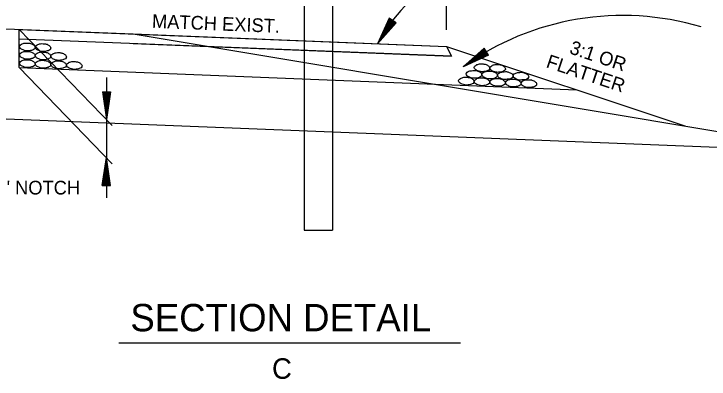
# Model space of a CAD drawing. Extents: x 1374136 to 1374281, y 380549 to 380948.
# Drawn here: x 1374151.8 to 1374182.29, y 380859.08 to 380875.1 of the extents above; entities that cross this region are included whole.
import ezdxf

# ---------------------------------------------------------------- set-up
doc = ezdxf.new("R2010")
doc.units = 0
doc.layers.add('Default', color=7, linetype='Continuous')
doc.layers.add('R_Draft', color=7, linetype='Continuous')

msp = doc.modelspace()

# ---------------------------------------------------------------- linework, layer by layer
at = {"layer": 'Default'}
for p, q in [((1374164.527, 380880.564), (1374164.527, 380865.616)), ((1374165.777, 380880.564), (1374165.777, 380865.616)), ((1374170.777, 380874.406), (1374170.777, 380876.243)), ((1374137.027, 380875.024), (1374157.027, 380874.224)), ((1374168.262, 380874.916), (1374167.748, 380873.795)), ((1374168.567, 380874.714), (1374167.748, 380873.795)), ((1374168.285, 380874.895), (1374167.86, 380873.967)), ((1374168.544, 380874.733), (1374167.86, 380873.967)), ((1374168.314, 380874.879), (1374167.974, 380874.143)), ((1374168.513, 380874.746), (1374167.974, 380874.143)), ((1374168.337, 380874.863), (1374168.083, 380874.31)), ((1374168.49, 380874.765), (1374168.083, 380874.31)), ((1374168.365, 380874.847), (1374168.197, 380874.484)), ((1374168.464, 380874.781), (1374168.197, 380874.484)), ((1374168.567, 380874.714), (1374168.262, 380874.916)), ((1374168.393, 380874.828), (1374168.311, 380874.653)), ((1374168.438, 380874.799), (1374168.311, 380874.653)), ((1374156.117, 380870.205), (1374152.027, 380874.424)), ((1374152.027, 380872.749), (1374152.027, 380874.424)), ((1374157.027, 380874.224), (1374170.777, 380873.674)), ((1374157.027, 380874.224), (1374194.756, 380867.936)), ((1374157.027, 380873.799), (1374170.994, 380873.241)), ((1374170.777, 380873.674), (1374181.227, 380870.191)), ((1374170.777, 380873.674), (1374170.994, 380873.241)), ((1374172.425, 380873.599), (1374171.502, 380872.784)), ((1374172.443, 380873.571), (1374171.674, 380872.893)), ((1374172.459, 380873.545), (1374171.848, 380873.008)), ((1374172.475, 380873.521), (1374172.018, 380873.119)), ((1374172.491, 380873.493), (1374172.19, 380873.23)), ((1374172.509, 380873.467), (1374172.365, 380873.341)), ((1374172.541, 380873.42), (1374172.365, 380873.341)), ((1374172.625, 380873.29), (1374172.425, 380873.599)), ((1374172.625, 380873.29), (1374171.502, 380872.784)), ((1374172.607, 380873.316), (1374171.674, 380872.893)), ((1374172.588, 380873.342), (1374171.848, 380873.008)), ((1374172.573, 380873.365), (1374172.018, 380873.119)), ((1374172.557, 380873.391), (1374172.19, 380873.23)), ((1374156.117, 380868.53), (1374152.027, 380872.749)), ((1374152.027, 380872.749), (1374176.488, 380871.771)), ((1374155.86, 380872.305), (1374155.86, 380867.029)), ((1374155.683, 380871.688), (1374155.86, 380870.471)), ((1374155.683, 380871.688), (1374156.045, 380871.687)), ((1374155.71, 380871.689), (1374155.859, 380870.672)), ((1374155.745, 380871.687), (1374155.861, 380870.889)), ((1374155.776, 380871.687), (1374155.861, 380871.09)), ((1374155.809, 380871.687), (1374155.863, 380871.292)), ((1374155.838, 380871.692), (1374155.864, 380871.497)), ((1374156.014, 380871.69), (1374155.859, 380870.672)), ((1374156.045, 380871.687), (1374155.86, 380870.471)), ((1374155.979, 380871.689), (1374155.861, 380870.889)), ((1374155.952, 380871.685), (1374155.861, 380871.09)), ((1374155.924, 380871.688), (1374155.863, 380871.292)), ((1374155.892, 380871.687), (1374155.864, 380871.497)), ((1374137.027, 380871.074), (1374188.212, 380869.027)), ((1374155.677, 380867.579), (1374155.86, 380868.796)), ((1374155.704, 380867.578), (1374155.858, 380868.594)), ((1374156.008, 380867.575), (1374155.858, 380868.594)), ((1374156.038, 380867.578), (1374155.86, 380868.796)), ((1374155.738, 380867.58), (1374155.859, 380868.377)), ((1374155.972, 380867.576), (1374155.859, 380868.377)), ((1374155.769, 380867.579), (1374155.858, 380868.176)), ((1374155.802, 380867.58), (1374155.859, 380867.974)), ((1374155.945, 380867.581), (1374155.858, 380868.176)), ((1374155.917, 380867.577), (1374155.859, 380867.974)), ((1374155.832, 380867.574), (1374155.858, 380867.769)), ((1374155.885, 380867.579), (1374155.858, 380867.769)), ((1374155.677, 380867.579), (1374156.038, 380867.578)), ((1374156.41, 380860.679), (1374171.395, 380860.679))]:
    msp.add_line(p, q, dxfattribs=at)
msp.add_lwpolyline([(1374152.027, 380873.999), (1374152.027, 380874.424), (1374170.777, 380873.674), (1374170.994, 380873.241)], close=True, dxfattribs=at)
for centre, radius, start, end in [((1374174.22, 380870.331), 7.341, 88.8267, 151.8416), ((1374178.504, 380863.012), 12.021, 73.3815, 125.6318)]:
    msp.add_arc(centre, radius, start, end, dxfattribs=at)
for points in [[(1374152.399, 380873.822), (1374152.279, 380873.821), (1374152.132, 380873.772), (1374152.062, 380873.707), (1374152.05, 380873.664), (1374152.085, 380873.59), (1374152.129, 380873.557), (1374152.205, 380873.519), (1374152.324, 380873.485), (1374152.383, 380873.48), (1374152.474, 380873.486), (1374152.573, 380873.503), (1374152.65, 380873.531), (1374152.72, 380873.588), (1374152.731, 380873.631), (1374152.71, 380873.697), (1374152.656, 380873.742), (1374152.606, 380873.779), (1374152.526, 380873.806), (1374152.475, 380873.818), (1374152.399, 380873.822)], [(1374153.085, 380873.795), (1374152.965, 380873.793), (1374152.818, 380873.744), (1374152.748, 380873.68), (1374152.736, 380873.636), (1374152.771, 380873.563), (1374152.815, 380873.529), (1374152.891, 380873.492), (1374153.01, 380873.457), (1374153.069, 380873.453), (1374153.16, 380873.458), (1374153.259, 380873.475), (1374153.336, 380873.503), (1374153.406, 380873.56), (1374153.417, 380873.604), (1374153.397, 380873.67), (1374153.343, 380873.714), (1374153.292, 380873.752), (1374153.212, 380873.778), (1374153.161, 380873.79), (1374153.085, 380873.795)], [(1374152.399, 380873.457), (1374152.279, 380873.456), (1374152.132, 380873.407), (1374152.062, 380873.342), (1374152.05, 380873.299), (1374152.085, 380873.225), (1374152.129, 380873.192), (1374152.205, 380873.154), (1374152.324, 380873.12), (1374152.383, 380873.115), (1374152.474, 380873.121), (1374152.573, 380873.138), (1374152.65, 380873.166), (1374152.72, 380873.223), (1374152.731, 380873.266), (1374152.71, 380873.332), (1374152.656, 380873.377), (1374152.606, 380873.414), (1374152.526, 380873.441), (1374152.475, 380873.453), (1374152.399, 380873.457)], [(1374153.085, 380873.43), (1374152.965, 380873.428), (1374152.818, 380873.379), (1374152.748, 380873.315), (1374152.736, 380873.271), (1374152.771, 380873.198), (1374152.815, 380873.164), (1374152.891, 380873.127), (1374153.01, 380873.092), (1374153.069, 380873.088), (1374153.16, 380873.093), (1374153.259, 380873.11), (1374153.336, 380873.138), (1374153.406, 380873.195), (1374153.417, 380873.239), (1374153.397, 380873.305), (1374153.343, 380873.349), (1374153.292, 380873.387), (1374153.212, 380873.413), (1374153.161, 380873.425), (1374153.085, 380873.43)], [(1374153.771, 380873.403), (1374153.651, 380873.401), (1374153.504, 380873.352), (1374153.434, 380873.287), (1374153.422, 380873.244), (1374153.458, 380873.17), (1374153.501, 380873.137), (1374153.577, 380873.099), (1374153.696, 380873.065), (1374153.755, 380873.06), (1374153.846, 380873.066), (1374153.945, 380873.083), (1374154.022, 380873.111), (1374154.092, 380873.168), (1374154.103, 380873.211), (1374154.083, 380873.277), (1374154.029, 380873.322), (1374153.978, 380873.359), (1374153.898, 380873.386), (1374153.847, 380873.398), (1374153.771, 380873.403)], [(1374152.399, 380873.092), (1374152.279, 380873.091), (1374152.132, 380873.042), (1374152.062, 380872.977), (1374152.05, 380872.934), (1374152.085, 380872.86), (1374152.129, 380872.827), (1374152.205, 380872.789), (1374152.324, 380872.755), (1374152.383, 380872.75), (1374152.474, 380872.756), (1374152.573, 380872.773), (1374152.65, 380872.801), (1374152.72, 380872.858), (1374152.731, 380872.901), (1374152.71, 380872.967), (1374152.656, 380873.012), (1374152.606, 380873.049), (1374152.526, 380873.076), (1374152.475, 380873.088), (1374152.399, 380873.092)], [(1374153.085, 380873.065), (1374152.965, 380873.063), (1374152.818, 380873.014), (1374152.748, 380872.95), (1374152.736, 380872.906), (1374152.771, 380872.833), (1374152.815, 380872.799), (1374152.891, 380872.762), (1374153.01, 380872.727), (1374153.069, 380872.723), (1374153.16, 380872.728), (1374153.259, 380872.745), (1374153.336, 380872.773), (1374153.406, 380872.83), (1374153.417, 380872.874), (1374153.397, 380872.94), (1374153.343, 380872.984), (1374153.292, 380873.022), (1374153.212, 380873.048), (1374153.161, 380873.06), (1374153.085, 380873.065)], [(1374153.771, 380873.038), (1374153.651, 380873.036), (1374153.504, 380872.987), (1374153.434, 380872.922), (1374153.422, 380872.879), (1374153.458, 380872.805), (1374153.501, 380872.772), (1374153.577, 380872.734), (1374153.696, 380872.7), (1374153.755, 380872.695), (1374153.846, 380872.701), (1374153.945, 380872.718), (1374154.022, 380872.746), (1374154.092, 380872.803), (1374154.103, 380872.846), (1374154.083, 380872.912), (1374154.029, 380872.957), (1374153.978, 380872.994), (1374153.898, 380873.021), (1374153.847, 380873.033), (1374153.771, 380873.038)], [(1374154.457, 380873.01), (1374154.337, 380873.008), (1374154.19, 380872.96), (1374154.12, 380872.895), (1374154.108, 380872.851), (1374154.144, 380872.778), (1374154.187, 380872.744), (1374154.263, 380872.707), (1374154.383, 380872.672), (1374154.441, 380872.668), (1374154.532, 380872.674), (1374154.631, 380872.69), (1374154.708, 380872.718), (1374154.778, 380872.775), (1374154.789, 380872.819), (1374154.769, 380872.885), (1374154.715, 380872.93), (1374154.664, 380872.967), (1374154.584, 380872.994), (1374154.534, 380873.005), (1374154.457, 380873.01)], [(1374172.342, 380872.907), (1374172.222, 380872.905), (1374172.075, 380872.857), (1374172.005, 380872.792), (1374171.994, 380872.748), (1374172.029, 380872.675), (1374172.072, 380872.641), (1374172.148, 380872.604), (1374172.268, 380872.569), (1374172.326, 380872.565), (1374172.417, 380872.571), (1374172.516, 380872.587), (1374172.593, 380872.615), (1374172.663, 380872.672), (1374172.675, 380872.716), (1374172.654, 380872.782), (1374172.6, 380872.827), (1374172.55, 380872.864), (1374172.47, 380872.891), (1374172.419, 380872.902), (1374172.342, 380872.907)], [(1374173.028, 380872.88), (1374172.908, 380872.878), (1374172.762, 380872.829), (1374172.691, 380872.765), (1374172.68, 380872.721), (1374172.715, 380872.648), (1374172.758, 380872.614), (1374172.834, 380872.576), (1374172.954, 380872.542), (1374173.012, 380872.537), (1374173.103, 380872.543), (1374173.202, 380872.56), (1374173.279, 380872.588), (1374173.349, 380872.645), (1374173.361, 380872.689), (1374173.34, 380872.754), (1374173.286, 380872.799), (1374173.236, 380872.836), (1374173.156, 380872.863), (1374173.105, 380872.875), (1374173.028, 380872.88)], [(1374171.998, 380872.623), (1374171.87, 380872.611), (1374171.728, 380872.577), (1374171.654, 380872.509), (1374171.642, 380872.469), (1374171.677, 380872.391), (1374171.721, 380872.358), (1374171.8, 380872.313), (1374171.916, 380872.282), (1374171.975, 380872.281), (1374172.066, 380872.287), (1374172.168, 380872.293), (1374172.245, 380872.328), (1374172.312, 380872.389), (1374172.323, 380872.436), (1374172.303, 380872.502), (1374172.249, 380872.547), (1374172.198, 380872.569), (1374172.118, 380872.603), (1374172.071, 380872.619), (1374171.998, 380872.623)], [(1374172.684, 380872.596), (1374172.556, 380872.583), (1374172.414, 380872.549), (1374172.34, 380872.481), (1374172.328, 380872.441), (1374172.364, 380872.364), (1374172.407, 380872.331), (1374172.486, 380872.286), (1374172.602, 380872.255), (1374172.661, 380872.254), (1374172.752, 380872.26), (1374172.854, 380872.265), (1374172.931, 380872.301), (1374172.998, 380872.362), (1374173.009, 380872.409), (1374172.989, 380872.475), (1374172.935, 380872.519), (1374172.884, 380872.542), (1374172.804, 380872.576), (1374172.757, 380872.591), (1374172.684, 380872.596)], [(1374173.37, 380872.569), (1374173.243, 380872.556), (1374173.1, 380872.522), (1374173.026, 380872.454), (1374173.014, 380872.414), (1374173.05, 380872.337), (1374173.093, 380872.303), (1374173.172, 380872.258), (1374173.288, 380872.227), (1374173.347, 380872.226), (1374173.438, 380872.232), (1374173.54, 380872.238), (1374173.617, 380872.273), (1374173.684, 380872.334), (1374173.696, 380872.381), (1374173.675, 380872.447), (1374173.621, 380872.492), (1374173.57, 380872.514), (1374173.49, 380872.549), (1374173.443, 380872.564), (1374173.37, 380872.569)], [(1374174.056, 380872.541), (1374173.929, 380872.529), (1374173.786, 380872.494), (1374173.712, 380872.426), (1374173.7, 380872.386), (1374173.736, 380872.309), (1374173.779, 380872.276), (1374173.858, 380872.231), (1374173.975, 380872.2), (1374174.033, 380872.199), (1374174.124, 380872.205), (1374174.226, 380872.21), (1374174.303, 380872.246), (1374174.37, 380872.307), (1374174.382, 380872.354), (1374174.361, 380872.42), (1374174.307, 380872.464), (1374174.256, 380872.487), (1374174.176, 380872.521), (1374174.129, 380872.536), (1374174.056, 380872.541)], [(1374171.653, 380872.322), (1374171.533, 380872.32), (1374171.387, 380872.272), (1374171.316, 380872.207), (1374171.305, 380872.164), (1374171.34, 380872.09), (1374171.383, 380872.057), (1374171.459, 380872.019), (1374171.579, 380871.984), (1374171.637, 380871.98), (1374171.728, 380871.986), (1374171.827, 380872.002), (1374171.904, 380872.03), (1374171.974, 380872.088), (1374171.986, 380872.131), (1374171.965, 380872.197), (1374171.911, 380872.242), (1374171.861, 380872.279), (1374171.781, 380872.306), (1374171.73, 380872.317), (1374171.653, 380872.322)], [(1374172.339, 380872.295), (1374172.219, 380872.293), (1374172.073, 380872.244), (1374172.002, 380872.18), (1374171.991, 380872.136), (1374172.026, 380872.063), (1374172.069, 380872.029), (1374172.145, 380871.992), (1374172.265, 380871.957), (1374172.323, 380871.952), (1374172.414, 380871.958), (1374172.513, 380871.975), (1374172.59, 380872.003), (1374172.66, 380872.06), (1374172.672, 380872.104), (1374172.651, 380872.17), (1374172.597, 380872.214), (1374172.547, 380872.251), (1374172.467, 380872.278), (1374172.416, 380872.29), (1374172.339, 380872.295)], [(1374173.026, 380872.267), (1374172.905, 380872.266), (1374172.759, 380872.217), (1374172.688, 380872.152), (1374172.677, 380872.109), (1374172.712, 380872.035), (1374172.755, 380872.002), (1374172.831, 380871.964), (1374172.951, 380871.929), (1374173.009, 380871.925), (1374173.101, 380871.931), (1374173.199, 380871.947), (1374173.276, 380871.975), (1374173.346, 380872.033), (1374173.358, 380872.076), (1374173.337, 380872.142), (1374173.283, 380872.187), (1374173.233, 380872.224), (1374173.153, 380872.251), (1374173.102, 380872.263), (1374173.026, 380872.267)], [(1374173.712, 380872.24), (1374173.591, 380872.238), (1374173.445, 380872.189), (1374173.374, 380872.125), (1374173.363, 380872.081), (1374173.398, 380872.008), (1374173.441, 380871.974), (1374173.517, 380871.937), (1374173.637, 380871.902), (1374173.695, 380871.897), (1374173.787, 380871.903), (1374173.885, 380871.92), (1374173.962, 380871.948), (1374174.032, 380872.005), (1374174.044, 380872.049), (1374174.023, 380872.115), (1374173.969, 380872.159), (1374173.919, 380872.197), (1374173.839, 380872.223), (1374173.788, 380872.235), (1374173.712, 380872.24)], [(1374174.398, 380872.212), (1374174.277, 380872.211), (1374174.131, 380872.162), (1374174.06, 380872.097), (1374174.049, 380872.054), (1374174.084, 380871.98), (1374174.127, 380871.947), (1374174.203, 380871.909), (1374174.323, 380871.875), (1374174.381, 380871.87), (1374174.473, 380871.876), (1374174.571, 380871.893), (1374174.648, 380871.921), (1374174.718, 380871.978), (1374174.73, 380872.021), (1374174.709, 380872.087), (1374174.655, 380872.132), (1374174.605, 380872.169), (1374174.525, 380872.196), (1374174.474, 380872.208), (1374174.398, 380872.212)]]:
    msp.add_spline(points, degree=3, dxfattribs=at)
at = {"layer": 'R_Draft'}
msp.add_line((1374164.527, 380865.616), (1374165.777, 380865.616), dxfattribs=at)

# ---------------------------------------------------------------- texts
at = {"layer": 'Default'}
for s, rotation, p in [('MATCH EXIST.', 357.7094, (1374157.849, 380874.492)), ('3:1 OR', 341.5651, (1374176.129, 380873.378)), ('FLATTER', 341.5651, (1374175.105, 380872.77))]:
    msp.add_text(s, height=0.6, rotation=rotation, dxfattribs=at).set_placement(p)
for s, height, p in [('8" NOTCH', 0.6, (1374150.899, 380867.18)), ('SECTION DETAIL', 1.2, (1374156.91, 380861.179)), ('C', 0.9, (1374163.123, 380859.095))]:
    msp.add_text(s, height=height, dxfattribs=at).set_placement(p)

doc.saveas('drawing.dxf')
